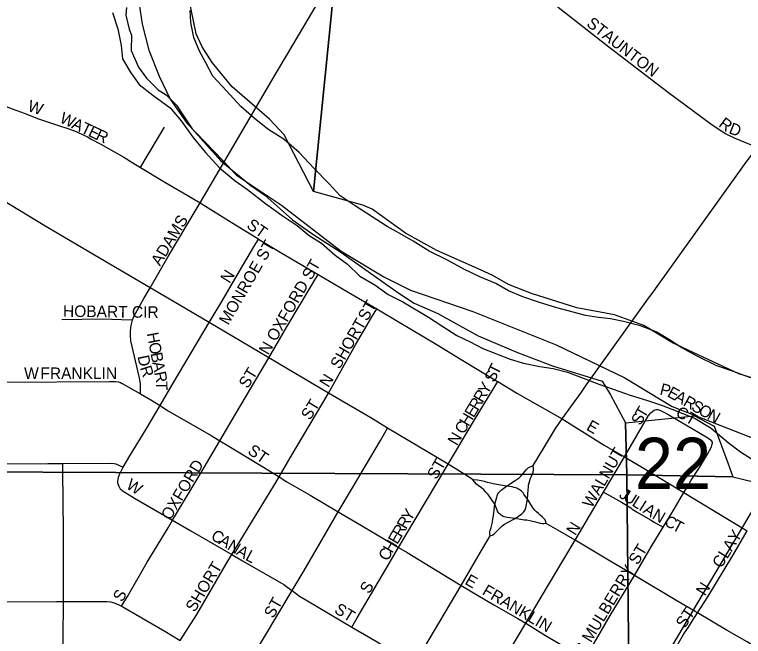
# Model space of a CAD drawing. Extents: x 0 to 680, y 0 to 440.
# Drawn here: x 480.88 to 491.37, y 328.65 to 337.6 of the extents above; entities that cross this region are included whole.
import ezdxf

# ---------------------------------------------------------------- set-up
doc = ezdxf.new("R2010")
doc.units = 0
for name, color, linetype in [('GM_X_City_Street', 7, 'Continuous'), ('GM_X_City_Street_Text', 7, 'Continuous'), ('GM_X_Major_River', 7, 'Continuous'), ('GM_X_Rail_Line', 7, 'Continuous'), ('GM_X_Section', 7, 'Continuous'), ('GM_X_Section_Text', 7, 'Continuous'), ('GM_X_State_Route', 7, 'Continuous'), ('GM_X_Township', 7, 'Continuous')]:
    doc.layers.add(name, color=color, linetype=linetype)

msp = doc.modelspace()

# ---------------------------------------------------------------- linework, layer by layer
at = {"layer": 'GM_X_City_Street'}
for points in [[(483.873, 335.438), (484.652, 336.765), (484.798, 337.015), (485.29, 337.844), (485.759, 338.648), (485.902, 338.859)], [(491.569, 335.689), (491.244, 335.821), (491.115, 335.885), (491.02, 335.942), (490.9, 336.022), (490.293, 336.474), (489.433, 337.13), (488.572, 337.804), (488.481, 337.871), (488.409, 337.935), (488.319, 338.018), (488.225, 338.112), (488.208, 338.13)], [(480.717, 336.294), (480.81, 336.259), (481.02, 336.181), (481.224, 336.101), (481.411, 336.036), (481.541, 335.993)], [(481.541, 335.993), (481.632, 335.963), (481.662, 335.955), (481.701, 335.943), (481.743, 335.927), (481.787, 335.907), (481.869, 335.867), (481.93, 335.839), (481.986, 335.808), (482.122, 335.736), (482.452, 335.55), (482.622, 335.445), (482.694, 335.401)], [(482.694, 335.401), (482.748, 335.492), (483.041, 335.979)], [(482.694, 335.401), (483.042, 335.189), (483.423, 334.968), (483.551, 334.889)], [(483.551, 334.889), (483.873, 335.438)], [(482.832, 333.671), (483.092, 334.119), (483.496, 334.795), (483.551, 334.889)], [(483.551, 334.889), (484, 334.612), (484.381, 334.378), (484.392, 334.371)], [(483.683, 333.168), (483.878, 333.498), (484.119, 333.908), (484.326, 334.26), (484.392, 334.371)], [(484.392, 334.371), (484.727, 334.169), (485.249, 333.862)], [(484.54, 332.662), (484.801, 333.106), (485.182, 333.749), (485.249, 333.862)], [(485.249, 333.862), (485.661, 333.62), (486.093, 333.366)], [(482.579, 333.207), (482.598, 333.258), (482.744, 333.515), (482.832, 333.671)], [(485.401, 332.155), (485.79, 332.848), (486.02, 333.24), (486.093, 333.366)], [(486.093, 333.366), (486.416, 333.177), (486.949, 332.858), (487.31, 332.638), (487.818, 332.333), (487.835, 332.323)], [(481.56, 333.215), (482.142, 333.223), (482.423, 333.212), (482.579, 333.207)], [(482.694, 332.144), (482.694, 332.174), (482.694, 332.284), (482.69, 332.318), (482.686, 332.352), (482.682, 332.368), (482.677, 332.391), (482.555, 332.906), (482.548, 332.984), (482.549, 333.052), (482.56, 333.129), (482.579, 333.205), (482.579, 333.207)], [(482.978, 331.974), (483.151, 332.275), (483.423, 332.736), (483.683, 333.168)], [(483.837, 331.469), (484.061, 331.85), (484.429, 332.473), (484.54, 332.662)], [(480.644, 332.31), (480.739, 332.311), (482.247, 332.322), (482.292, 332.322), (482.333, 332.321), (482.372, 332.315), (482.404, 332.305), (482.43, 332.292), (482.694, 332.144)], [(487.122, 331.131), (487.501, 331.771), (487.768, 332.212), (487.835, 332.323)], [(487.835, 332.323), (488.118, 332.15), (488.761, 331.784)], [(482.694, 332.144), (482.845, 332.06), (482.978, 331.974)], [(484.688, 330.949), (484.85, 331.222), (485.319, 332.016), (485.401, 332.155)], [(482.446, 331.089), (482.543, 331.25), (482.774, 331.634), (482.978, 331.974)], [(482.978, 331.974), (483.083, 331.905), (483.713, 331.545), (483.837, 331.469)], [(489.658, 331.237), (489.658, 331.238), (490.005, 331.831), (490.041, 331.872), (490.066, 331.895), (490.085, 331.908), (490.101, 331.916)], [(490.101, 331.916), (490.121, 331.921), (490.141, 331.918), (490.168, 331.909), (490.205, 331.892), (490.299, 331.841), (490.625, 331.651), (490.754, 331.574), (490.86, 331.51), (490.88, 331.496), (490.899, 331.482), (490.914, 331.462), (490.92, 331.447), (490.922, 331.423)], [(488.761, 331.784), (489.369, 331.407), (489.658, 331.237)], [(485.541, 330.447), (485.745, 330.793), (486.146, 331.475), (486.251, 331.652)], [(483.156, 330.325), (483.595, 331.059), (483.837, 331.469)], [(483.837, 331.469), (483.964, 331.391), (484.551, 331.035), (484.688, 330.949)], [(490.516, 330.727), (490.57, 330.818), (490.62, 330.901), (490.738, 331.086), (490.853, 331.278), (490.91, 331.383), (490.916, 331.401), (490.922, 331.423)], [(489.356, 330.728), (489.658, 331.237)], [(489.658, 331.237), (489.942, 331.07), (490.516, 330.727)], [(480.626, 331.138), (481.359, 331.14), (481.577, 331.142)], [(481.577, 331.142), (482.261, 331.147), (482.315, 331.143), (482.338, 331.138), (482.446, 331.089)], [(481.584, 329.155), (481.584, 329.167), (481.586, 329.685), (481.586, 330.162), (481.578, 331.036), (481.577, 331.142)], [(482.37, 330.854), (482.369, 330.884), (482.371, 330.915), (482.377, 330.945), (482.391, 330.984), (482.446, 331.089)], [(486.409, 329.935), (486.648, 330.338), (487.122, 331.131)], [(484.007, 329.831), (484.191, 330.131), (484.614, 330.822), (484.688, 330.949)], [(484.688, 330.949), (484.801, 330.877), (485.136, 330.686), (485.541, 330.447)], [(482.37, 330.854), (482.375, 330.832), (482.382, 330.815), (482.392, 330.795), (482.402, 330.779), (482.415, 330.766), (482.432, 330.752), (482.606, 330.644), (483.156, 330.325)], [(488.948, 330.037), (489.218, 330.495), (489.356, 330.728)], [(489.356, 330.728), (489.41, 330.7), (489.452, 330.679), (489.615, 330.585), (489.75, 330.502), (489.772, 330.486), (489.843, 330.441), (490.032, 330.331), (490.086, 330.299), (490.216, 330.224)], [(490.216, 330.224), (490.373, 330.485), (490.516, 330.727)], [(490.516, 330.727), (490.942, 330.467), (491.425, 330.173)], [(484.875, 329.315), (485.048, 329.603), (485.361, 330.14), (485.541, 330.447)], [(485.541, 330.447), (485.874, 330.25), (486.409, 329.935)], [(482.422, 329.09), (482.505, 329.231), (482.791, 329.721), (483.09, 330.215), (483.156, 330.325)], [(483.156, 330.325), (483.419, 330.172), (484.007, 329.831)], [(489.802, 329.529), (489.89, 329.678), (490.044, 329.941), (490.216, 330.224)], [(490.708, 328.995), (490.859, 329.222), (491.218, 329.821), (491.425, 330.173)], [(488.238, 328.844), (488.434, 329.172), (488.948, 330.037)], [(485.736, 328.79), (485.812, 328.921), (486.224, 329.622), (486.409, 329.935)], [(486.409, 329.935), (486.531, 329.863), (487.31, 329.385)], [(483.267, 328.594), (483.503, 328.97), (483.92, 329.689), (484.007, 329.831)], [(484.007, 329.831), (484.163, 329.74), (484.755, 329.4), (484.872, 329.317), (484.875, 329.315)], [(489.088, 328.328), (489.15, 328.435), (489.454, 328.957), (489.802, 329.529)], [(487.31, 329.385), (487.777, 329.111), (488.125, 328.912), (488.238, 328.844)], [(484.133, 328.076), (484.478, 328.651), (484.875, 329.315)], [(484.875, 329.315), (484.984, 329.233), (485.096, 329.165), (485.736, 328.79)], [(480.385, 329.156), (480.639, 329.154), (481.486, 329.155), (481.584, 329.155)], [(481.576, 327.48), (481.576, 327.488), (481.579, 327.718), (481.582, 328.189), (481.582, 328.622), (481.584, 329.155)], [(481.584, 329.155), (481.825, 329.156), (482.157, 329.158), (482.213, 329.156), (482.262, 329.15), (482.317, 329.136), (482.38, 329.111), (482.422, 329.09)], [(482.422, 329.09), (482.44, 329.08), (483.043, 328.731), (483.267, 328.594)], [(489.987, 327.798), (490.143, 328.062), (490.326, 328.364), (490.516, 328.69), (490.579, 328.786), (490.632, 328.872), (490.708, 328.995)], [(487.557, 327.711), (487.646, 327.854), (488.119, 328.645), (488.238, 328.844)], [(488.238, 328.844), (488.524, 328.67), (488.779, 328.521), (488.987, 328.395), (489.088, 328.328)], [(485.736, 328.79), (486.098, 328.578), (486.634, 328.25)]]:
    msp.add_lwpolyline(points, dxfattribs=at)
at = {"layer": 'GM_X_Major_River'}
for points in [[(491.2, 332.474), (490.988, 332.546), (490.717, 332.679), (490.486, 332.805), (490.308, 332.923), (490.117, 333.035), (489.891, 333.12), (489.645, 333.186), (489.459, 333.224), (489.286, 333.241), (489.099, 333.272), (488.866, 333.331), (488.687, 333.382), (488.421, 333.462), (488.196, 333.541), (487.99, 333.626), (487.806, 333.73), (487.58, 333.829), (487.349, 333.935), (487.111, 334.067), (486.847, 334.194), (486.616, 334.34), (486.425, 334.451), (486.246, 334.549), (486.029, 334.688), (485.785, 334.847), (485.568, 334.993), (485.411, 335.163), (485.189, 335.389), (484.98, 335.615), (484.764, 335.8), (484.527, 335.953), (484.33, 336.111), (484.14, 336.276), (483.931, 336.502), (483.735, 336.714), (483.633, 336.903), (483.543, 337.072), (483.46, 337.268), (483.419, 337.483), (483.409, 337.657)], [(482.292, 337.63), (482.367, 337.394), (482.414, 337.152), (482.437, 336.964), (482.553, 336.761), (482.676, 336.591), (482.873, 336.439), (483.123, 336.26), (483.279, 336.069), (483.447, 335.838), (483.629, 335.613), (483.832, 335.394), (484.055, 335.208), (484.232, 335.084), (484.495, 334.884), (484.732, 334.711), (484.949, 334.566), (485.12, 334.421), (485.298, 334.31), (485.494, 334.139), (485.672, 334.007), (485.849, 333.836), (486.066, 333.711), (486.257, 333.573), (486.469, 333.467), (486.838, 333.245), (487.029, 333.12), (487.247, 332.981), (487.438, 332.89), (487.623, 332.798), (487.816, 332.72), (488.014, 332.642), (488.207, 332.584), (488.44, 332.539), (488.633, 332.507), (488.839, 332.456), (489.078, 332.363), (489.29, 332.285), (489.496, 332.213), (489.741, 332.127), (489.974, 332.055), (490.193, 331.983), (490.425, 331.891), (490.676, 331.791), (490.907, 331.652), (491.15, 331.446), (491.327, 331.308), (491.538, 331.176)], [(491.572, 332.345), (491.433, 332.389), (491.2, 332.474)]]:
    msp.add_lwpolyline(points, dxfattribs=at)
at = {"layer": 'GM_X_Rail_Line'}
msp.add_lwpolyline([(492.717, 332.516), (490.623, 328.994), (489.818, 327.634), (488.984, 326.25), (488.832, 325.981), (488.751, 325.816), (488.679, 325.663), (488.619, 325.509), (488.55, 325.316), (488.504, 325.171), (488.461, 325.005), (488.422, 324.838), (488.379, 324.626), (488.346, 324.449), (488.323, 324.222), (488.309, 323.969), (488.308, 323.694), (488.321, 323.425), (488.351, 323.194), (488.397, 322.914), (488.532, 322.319), (488.76, 321.376), (488.94, 320.609)], dxfattribs=at)
at = {"layer": 'GM_X_Section'}
for points in [[(485.85, 341.665), (485.186, 335.056), (484.76, 335.871), (484.551, 336.096), (484.406, 336.218), (484.012, 336.559), (483.725, 336.912), (483.583, 337.135), (483.493, 337.323), (483.389, 337.839), (483.408, 338.153), (483.455, 338.526), (483.438, 338.673), (483.41, 338.947), (483.423, 339.301), (483.393, 339.468), (483.363, 340.022), (483.323, 340.384), (483.244, 340.792), (483.215, 341.06), (482.872, 341.954)], [(489.695, 330.98), (489.676, 331.728), (490.667, 331.829), (490.952, 331.678), (491.145, 331.15), (491.217, 330.951)], [(489.695, 330.98), (489.874, 313.088), (471.837, 312.991), (471.834, 331.06)]]:
    msp.add_lwpolyline(points, close=True, dxfattribs=at)
for points in [[(491.696, 332.311), (491.304, 332.432), (490.351, 332.877), (489.936, 333.125), (489.518, 333.279), (488.972, 333.383), (488.322, 333.589), (487.991, 333.715), (487.766, 333.846), (487.588, 333.929), (486.959, 334.208), (486.51, 334.457), (486.029, 334.8), (485.896, 334.856), (485.186, 335.056), (485.85, 341.665), (503.581, 339.978)], [(482.492, 337.703), (482.483, 337.589), (482.533, 337.388), (482.564, 337.301), (482.56, 337.081), (482.663, 336.845), (482.78, 336.683), (482.95, 336.519), (483.062, 336.444), (483.213, 336.294), (483.304, 336.159), (483.44, 335.956), (483.852, 335.494), (484.28, 335.139), (484.484, 335.002), (484.884, 334.648), (485.174, 334.442), (485.577, 334.181), (486.084, 333.824), (486.413, 333.591), (486.631, 333.447), (486.975, 333.3), (487.556, 332.976), (488.119, 332.738), (488.623, 332.548), (489.34, 332.328), (489.456, 332.132), (489.676, 331.728), (489.695, 330.98), (471.834, 331.06)], [(489.874, 313.088), (489.695, 330.98), (491.217, 330.951), (492.745, 330.582)]]:
    msp.add_lwpolyline(points, dxfattribs=at)
at = {"layer": 'GM_X_State_Route'}
for points in [[(482.114, 334.092), (481.334, 334.55), (480.686, 334.945), (480.263, 335.203), (479.272, 335.789), (478.626, 336.171), (477.637, 336.754), (477.183, 337.019), (476.051, 337.68), (475.689, 337.891), (474.823, 338.397), (474.034, 338.859), (473.564, 339.135), (473.034, 339.447), (472.656, 339.669), (471.071, 340.602), (469.854, 341.32), (468.952, 341.852)], [(490.056, 333.587), (491.389, 335.444), (491.569, 335.689)], [(487.477, 330.908), (487.437, 330.935), (487.122, 331.131), (486.251, 331.652), (486.008, 331.797), (485.401, 332.155), (484.54, 332.662), (484.023, 332.967), (483.683, 333.168), (483.088, 333.52), (482.832, 333.671), (482.114, 334.092)], [(489.039, 332.17), (489.109, 332.267), (490.021, 333.537), (490.025, 333.543), (490.056, 333.587)], [(488.346, 331.111), (488.492, 331.356), (488.666, 331.643), (488.761, 331.784), (489.039, 332.17)], [(487.727, 330.102), (487.721, 330.13), (487.72, 330.149), (487.723, 330.168), (487.729, 330.187), (487.739, 330.22), (487.751, 330.258), (487.76, 330.3), (487.767, 330.347), (487.772, 330.39), (487.794, 330.556), (487.821, 330.659), (487.826, 330.676), (487.832, 330.691), (487.839, 330.704), (487.848, 330.718), (487.858, 330.73), (487.869, 330.744), (487.883, 330.756), (487.962, 330.817), (488.084, 330.896), (488.114, 330.916), (488.145, 330.937), (488.171, 330.963), (488.2, 330.996), (488.229, 331.034), (488.25, 331.058), (488.275, 331.079), (488.346, 331.111)], [(488.262, 330.628), (488.274, 330.769), (488.276, 330.799), (488.28, 330.829), (488.286, 330.862), (488.295, 330.897), (488.307, 330.93), (488.32, 330.961), (488.337, 330.995), (488.346, 331.015), (488.351, 331.039), (488.351, 331.065), (488.346, 331.111)], [(488.262, 330.628), (488.212, 330.703), (488.202, 330.718), (488.19, 330.732), (488.176, 330.745), (488.16, 330.757), (488.143, 330.769), (488.124, 330.778), (488.108, 330.785), (488.089, 330.793), (488.071, 330.798), (488.045, 330.804), (487.962, 330.817), (487.77, 330.849), (487.729, 330.857), (487.687, 330.868), (487.644, 330.883), (487.599, 330.894), (487.546, 330.902), (487.477, 330.908)], [(488.532, 330.281), (488.498, 330.273), (488.474, 330.273), (488.45, 330.277), (488.417, 330.287), (488.382, 330.299), (488.336, 330.31), (488.295, 330.318), (488.254, 330.325), (488.218, 330.329), (488.084, 330.352), (487.97, 330.363), (487.949, 330.368), (487.929, 330.375), (487.913, 330.382), (487.898, 330.391), (487.887, 330.398), (487.875, 330.407), (487.863, 330.416), (487.853, 330.426), (487.842, 330.44), (487.833, 330.455), (487.825, 330.473), (487.794, 330.556), (487.696, 330.694), (487.666, 330.732), (487.637, 330.765), (487.597, 330.795), (487.559, 330.823), (487.529, 330.845), (487.5, 330.876), (487.477, 330.908)], [(487.727, 330.102), (487.756, 330.111), (487.781, 330.125), (487.81, 330.153), (487.838, 330.184), (487.864, 330.213), (487.901, 330.244), (487.934, 330.268), (487.968, 330.289), (488.084, 330.352), (488.182, 330.418), (488.199, 330.435), (488.211, 330.448), (488.22, 330.461), (488.228, 330.475), (488.235, 330.49), (488.24, 330.506), (488.262, 330.628)], [(488.532, 330.281), (488.526, 330.305), (488.516, 330.33), (488.501, 330.349), (488.479, 330.369), (488.442, 330.405), (488.421, 330.424), (488.395, 330.446), (488.369, 330.47), (488.347, 330.498), (488.262, 330.628)], [(490.678, 329.012), (490.412, 329.167), (489.802, 329.529), (489.404, 329.765), (488.948, 330.037), (488.701, 330.182), (488.532, 330.281)], [(486.238, 327.584), (486.457, 327.952), (486.634, 328.25), (486.849, 328.612), (487.31, 329.385), (487.556, 329.811), (487.727, 330.102)], [(491.533, 328.512), (491.423, 328.576), (491.138, 328.74), (490.708, 328.995), (490.678, 329.012)]]:
    msp.add_lwpolyline(points, dxfattribs=at)
at = {"layer": 'GM_X_Township'}
for points in [[(482.673, 337.747), (482.716, 337.462), (482.815, 337.085), (482.963, 336.712), (483.122, 336.383), (483.365, 336.034), (483.877, 335.499), (484.075, 335.291), (484.725, 334.856), (485.581, 334.195), (486.198, 333.828), (486.582, 333.633), (487.476, 333.327), (488.675, 332.85), (489.266, 332.567), (489.666, 332.375), (490.344, 331.964), (491.585, 331.478)], [(482.673, 337.747), (482.716, 337.462), (482.815, 337.085), (482.963, 336.712), (483.122, 336.383), (483.365, 336.034), (484.075, 335.291), (484.725, 334.856), (485.581, 334.195), (486.198, 333.828), (486.582, 333.633), (487.476, 333.327), (488.675, 332.85), (489.666, 332.375), (490.344, 331.964), (491.585, 331.478)]]:
    msp.add_lwpolyline(points, dxfattribs=at)

# ---------------------------------------------------------------- texts
at = {"layer": 'GM_X_City_Street_Text'}
for s, height, rotation, p in [('STAUNTON', 0.1669, 322.0561, (489.101, 337.446)), ('W', 0.167, 341.5596, (481.058, 336.217)), ('W', 0.167, 334.6154, (481.517, 336.054)), ('A', 0.167, 334.5883, (481.69, 335.972)), ('R', 0.167, 323.0815, (491.003, 336)), ('T', 0.167, 334.6211, (481.822, 335.909)), ('E', 0.167, 334.62, (481.929, 335.859)), ('D', 0.167, 338.3321, (491.15, 335.897)), ('R', 0.167, 335.3366, (482.037, 335.808)), ('ADAMS', 0.1669, 58.8393, (482.975, 333.972)), ('ST', 0.1669, 325.2979, (484.209, 334.539)), ('MONROE ST', 0.1669, 59.8979, (483.957, 333.122)), ('N OXFORD ST', 0.16689, 60.0184, (484.531, 332.693)), ('N', 0.167, 57.9872, (483.974, 333.722)), ('ST', 0.1669, 60.2585, (485.957, 333.179)), ('HOBART CIR', 0.1669, 359.3094, (481.578, 333.252)), ('SHORT', 0.1669, 60.0988, (485.559, 332.488)), ('H', 0.167, 280.7741, (482.784, 333.013)), ('O', 0.167, 280.7984, (482.811, 332.869)), ('B', 0.167, 280.7718, (482.838, 332.725)), ('D', 0.167, 281.3742, (482.65, 332.683)), ('W', 0.167, 0, (481.019, 332.356)), ('FRANKLIN', 0.1669, 0, (481.254, 332.356)), ('R', 0.167, 287.9734, (482.684, 332.519)), ('A', 0.167, 280.7984, (482.863, 332.595)), ('ST', 0.1669, 58.3831, (484.238, 332.209)), ('T', 0.167, 63.4148, (487.837, 332.402)), ('R', 0.167, 280.7718, (482.891, 332.451)), ('N', 0.167, 57.9872, (485.398, 332.224)), ('S', 0.167, 63.3074, (487.784, 332.297)), ('T', 0.167, 270.4645, (482.915, 332.329)), ('Y', 0.167, 60.3433, (487.687, 332.122)), ('R', 0.167, 59.207, (487.617, 332.005)), ('P', 0.167, 345.6722, (490.158, 332.138)), ('E', 0.167, 331.516, (490.262, 332.112)), ('A', 0.167, 330.5018, (490.364, 332.057)), ('R', 0.167, 330.4901, (490.492, 331.984)), ('ST', 0.1669, 58.3953, (485.134, 331.754)), ('E', 0.167, 59.1909, (487.489, 331.79)), ('R', 0.167, 59.2175, (487.549, 331.891)), ('S', 0.167, 330.4985, (490.607, 331.919)), ('T', 0.167, 59.486, (489.947, 331.781)), ('CT', 0.1669, 329.0384, (490.383, 331.835)), ('O', 0.167, 330.5095, (490.709, 331.861)), ('N', 0.167, 330.5208, (490.837, 331.789)), ('H', 0.167, 59.2087, (487.414, 331.664)), ('S', 0.167, 61.1126, (489.891, 331.679)), ('C', 0.167, 59.2175, (487.346, 331.551)), ('E', 0.167, 330.245, (489.098, 331.633)), ('N', 0.167, 59.2087, (487.248, 331.387)), ('ST', 0.1669, 325.2979, (484.224, 331.293)), ('WALNUT', 0.1669, 59.8582, (489.187, 330.49)), ('OXFORD', 0.1669, 59.1865, (483.122, 330.314)), ('ST', 0.1669, 60.2568, (486.954, 330.901)), ('W', 0.167, 327.5237, (482.475, 330.795)), ('J', 0.167, 327.4618, (489.569, 330.663)), ('U', 0.167, 327.4499, (489.631, 330.623)), ('L', 0.167, 327.4662, (489.755, 330.544)), ('I', 0.167, 327.4679, (489.854, 330.481)), ('A', 0.167, 327.4653, (489.915, 330.441)), ('Y', 0.167, 58.5228, (486.582, 330.297)), ('N', 0.167, 329.8797, (490.046, 330.358)), ('R', 0.167, 59.8152, (486.516, 330.184)), ('C', 0.167, 331.6771, (490.217, 330.261)), ('T', 0.167, 331.6927, (490.333, 330.198)), ('R', 0.167, 59.8202, (486.449, 330.069)), ('N', 0.167, 58.0069, (488.952, 330.095)), ('CLAY', 0.1669, 58.2389, (491.052, 329.624)), ('C', 0.167, 328.803, (483.694, 330.061)), ('A', 0.167, 328.8169, (483.807, 329.992)), ('E', 0.167, 59.8146, (486.39, 329.968)), ('N', 0.167, 328.7963, (483.932, 329.916)), ('H', 0.167, 59.797, (486.316, 329.841)), ('S MULBERRY ST', 0.16689, 58.9466, (489.069, 328.375)), ('A', 0.167, 329.4161, (484.06, 329.839)), ('L', 0.167, 331.5641, (484.192, 329.761)), ('C', 0.167, 59.8152, (486.25, 329.727)), ('SHORT', 0.1669, 59.0386, (483.474, 328.993)), ('E', 0.167, 330.2686, (487.35, 329.415)), ('S', 0.167, 60.2686, (485.985, 329.256)), ('FRANKLIN', 0.1669, 329.4509, (487.6, 329.268)), ('N', 0.167, 57.9872, (490.818, 329.228)), ('S', 0.167, 60.2686, (482.431, 329.139)), ('ST', 0.1669, 60.2568, (484.605, 328.904)), ('ST', 0.1669, 328.3953, (485.471, 329.003)), ('ST', 0.1669, 56.3032, (490.524, 328.759))]:
    msp.add_text(s, height=height, rotation=rotation, dxfattribs=at).set_placement(p)
at = {"layer": 'GM_X_Section_Text'}
msp.add_text('22', height=0.7377, rotation=0, dxfattribs=at).set_placement((489.809, 330.775))

doc.saveas('drawing.dxf')
